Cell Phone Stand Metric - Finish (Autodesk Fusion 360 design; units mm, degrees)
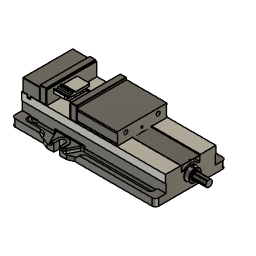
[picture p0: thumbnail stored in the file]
description: HaasClamp
derived_base_feature "Derived Base Feature" bodies "Stand Body"
align "Align1"
base_feature "Base Feature1"
base_feature "Base Feature1"
base_feature "Base Feature1"
base_feature "Base Feature1"
base_feature "Base Feature1"
base_feature "Base Feature1"
base_feature "Base Feature1"
base_feature "Base Feature1"
base_feature "Base Feature1"
base_feature "Base Feature1"
as_built_joint "As-built1"
as_built_joint "As-built2"
as_built_joint "As-built3"
joint_origin "JointOrigin1" OffsetX 0 OffsetY 0 OffsetZ 0 AngleZ 0
joint "Assemble1" alignAngle 180 alignOffsetX 0 alignOffsetY 0 alignOffsetZ 0 (= "jaw_width_haas_050002") SlideMaximum 22.5 SlideMinimum 0
position "Position1"
sketch "Sketch1" plane through (0, -72.5, 0) normal (0, -1, 0) x axis (1, 0, 0)
  line L1 (75, 73) -> (-75, 73)
  line L2 (76, 74) -> (75, 73)
  line L3 (76, 116.5) -> (76, 74)
  line L4 (75, 117.5) -> (76, 116.5)
  line L5 (-75, 117.5) -> (75, 117.5)
  line L6 (-76, 116.5) -> (-75, 117.5)
  line L7 (-76, 74) -> (-76, 116.5)
  line L8 (-75, 73) -> (-76, 74)
  line L9 (76.4, 114.275) -> (-76, 114.275)
  line L10 (76.4, 73) -> (76.4, 114.275)
  line L11 (-76, 73) -> (76.4, 73)
  line L12 (-76, 114.275) -> (-76, 73)
  circle C1 centre (49.21, 96.8) radius 11
  circle C2 centre (-49.21, 96.8) radius 11
  point P14 (76.4, 73)
  point P12 (-76, 114.275)
  point P13 (76.4, 114.275)
  horizontal L9
  vertical L10
  horizontal L11
  vertical L12
  coincident L1 P14
  coincident L7 P12
  dimension "d16" distance P12 P13 = 152.4
  dimension "d17" distance P13 P14 = 41.275
place_component sketch "Sketch1"
extrude "Extrude1" new body sketch "Sketch1" profile of L1 L2 L3 L7 L8 C1 C2 L9 L11 L12 along normal blind 3.175
place_component sketch "Sketch1"
extrude "Extrude1" sketch "Sketch1" profile of L1 L2 L3 L7 L8 C1 C2 L9 L11 L12 blind -3.175
as_built_joint "As-built5"
as_built_joint "As-built6"
sketch "Sketch1" plane through (0, 0, 0) normal (0, 0, -1) x axis (1, 0, 0)
  line L1 (16.5, -37.5) -> (-16.5, -37.5)
  line L2 (20, 34) -> (20, -34)
  line L3 (-16.5, 37.5) -> (16.5, 37.5)
  line L4 (-20, -34) -> (-20, 34)
  line L5 (-38.1, -40) -> (38.1, -40)
  line L6 (-38.1, 40) -> (-38.1, -40)
  line L7 (38.1, 40) -> (-38.1, 40)
  line L8 (38.1, -40) -> (38.1, 40)
  line L9 (-38.1, 40) -> (38.1, -40)
  line L10 (38.1, 40) -> (-38.1, -40)
  arc A1 centre (-16.5, -34) radius 3.5 clockwise from (-16.5, -37.5) to (-20, -34)
  arc A2 centre (16.5, -34) radius 3.5 clockwise from (20, -34) to (16.5, -37.5)
  arc A3 centre (16.5, 34) radius 3.5 clockwise from (16.5, 37.5) to (20, 34)
  arc A4 centre (-16.5, 34) radius 3.5 clockwise from (-20, 34) to (-16.5, 37.5)
  point P18 (0, 0)
  point P1 (0, 0)
  point P16 (-38.1, 40)
  point P17 (38.1, 40)
  point P15 (-38.1, -40)
  horizontal L5
  perpendicular L5 L6
  parallel L5 L7
  parallel L6 L8
  coincident L9 P18
  coincident L10 P18
  coincident P1 P18
  dimension "d1" distance P16 P17 = 76.2
  dimension "d2" distance P15 P16 = 80
extrude "Extrude1" new body sketch "Sketch1" profile of A1 L1 A2 L2 A3 L3 A4 L4 L5 L6 L7 L8 against normal blind 10 bodies "Stock"
position "Position1"
ground "Pin"
position "Position2"
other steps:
create_component "CreateComponent1"
create_component "CreateComponent2"
create_component "CreateComponent3"
create_component "CreateComponent4"
create_component "CreateComponent5"
create_component "CreateComponent6"
create_component "CreateComponent7"
create_component "CreateComponent8"
create_component "CreateComponent9"
create_component "CreateComponent10"
joint_origin "JointOrigin10"
joint_origin "JointOrigin11"
create_component "CreateComponent11" sketch "Sketch1"
create_component "CreateComponent12" sketch "Sketch1"
create_component "CreateComponent1"
named bodies: "Stand Body", "Stock"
